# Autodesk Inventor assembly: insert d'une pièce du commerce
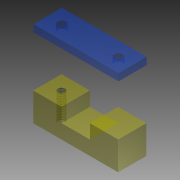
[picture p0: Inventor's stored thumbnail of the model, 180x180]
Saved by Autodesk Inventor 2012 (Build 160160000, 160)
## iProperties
Created: 2013-09
Part Number: insert d'une pièce du commerce
Document SubType Name: Assembly
Designer: hilarion
Author: hilarion
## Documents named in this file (3)
- D:\dominique\travail\année 2013-2014\TSTI2D\ITEC\activité 3 moulage projecteur imov\mode opératoire insert d'une pièce du commerce\insert d'une pièce du commerce.iam
- D:\dominique\travail\année 2013-2014\TSTI2D\ITEC\activité 3 moulage projecteur imov\mode opératoire insert d'une pièce du commerce\cube.ipt
- D:\dominique\travail\année 2013-2014\TSTI2D\ITEC\activité 3 moulage projecteur imov\mode opératoire insert d'une pièce du commerce\tole.ipt
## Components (2 placed, 2 different names)
1. cube:1
2. tole:1
